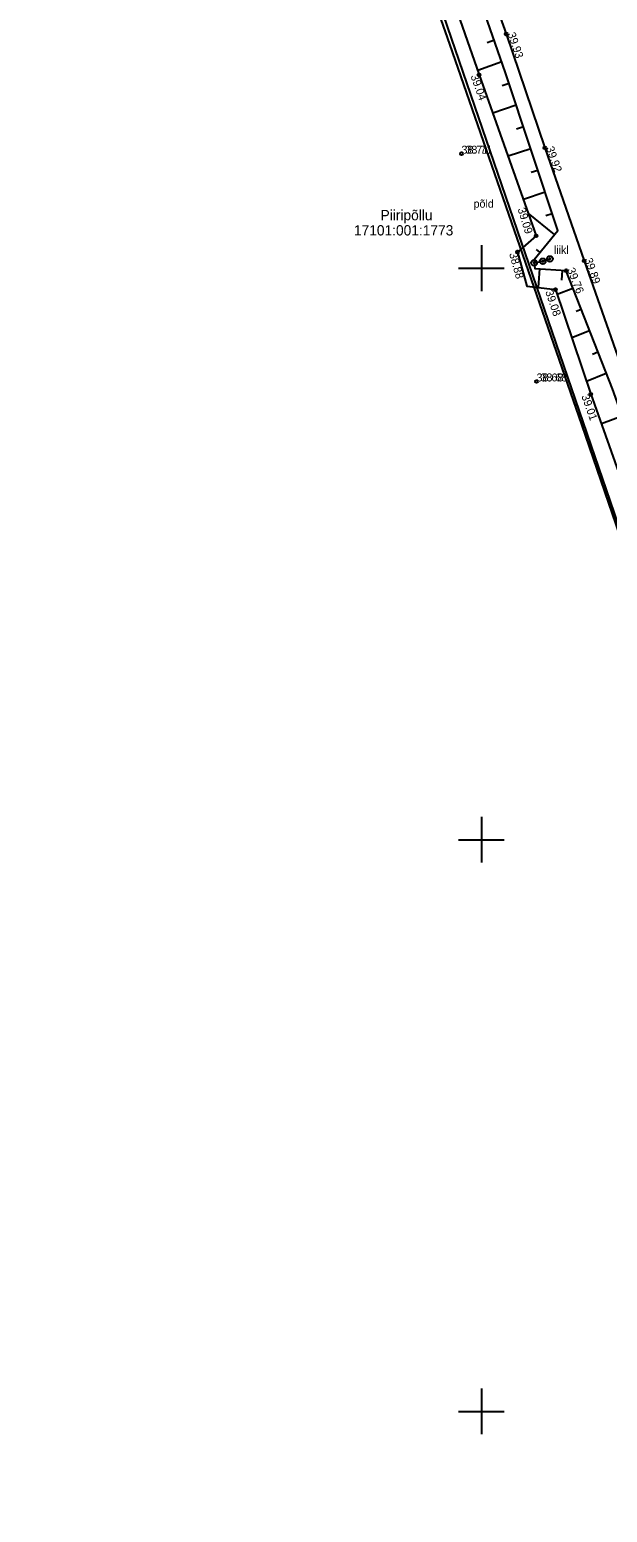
# Model space of a CAD drawing. Extents: x 627548 to 628052, y 6467984 to 6468802.
# Drawn here: x 627910.5 to 627961, y 6467991.2 to 6468120.9 of the extents above; entities that cross this region are included whole.
import ezdxf

# ---------------------------------------------------------------- set-up
doc = ezdxf.new("R2010")
doc.units = 0
for name, color, linetype in [('HALJASTUS', 7, 'Continuous'), ('KORGUS-EH2000', 7, 'Continuous'), ('LIIKLUS', 7, 'Continuous'), ('MOOTKORG-EH2000', 7, 'Continuous'), ('MOOTMPUNKT', 7, 'Continuous'), ('PIIR', 7, 'Continuous'), ('RELJEEF', 7, 'Continuous'), ('SITRASS', 7, 'Continuous'), ('TEE', 7, 'Continuous'), ('VORK', 7, 'Continuous')]:
    doc.layers.add(name, color=color, linetype=linetype)

msp = doc.modelspace()

# ---------------------------------------------------------------- linework, layer by layer
at = {"layer": 'KORGUS-EH2000'}
for centre in [(627952.16, 6468120.49), (627949.81, 6468116.9), (627955.55, 6468110.52), (627954.8, 6468102.83), (627953.15, 6468101.41), (627958.99, 6468100.64), (627957.41, 6468099.78), (627956.49, 6468098.12), (627959.58, 6468088.97)]:
    msp.add_circle(centre, 0.125, dxfattribs=at)
at = {"layer": 'LIIKLUS'}
msp.add_lwpolyline([(627954.61, 6468100.46), (627955.37, 6468100.6), (627955.99, 6468100.81)], dxfattribs=at)
for centre, radius in [((627954.61, 6468100.46), 0.25), ((627954.61, 6468100.46), 0.05), ((627955.37, 6468100.6), 0.25), ((627955.37, 6468100.6), 0.05), ((627955.99, 6468100.81), 0.25), ((627955.99, 6468100.81), 0.05)]:
    msp.add_circle(centre, radius, dxfattribs=at)
at = {"layer": 'MOOTMPUNKT'}
for centre in [(627948.25, 6468110.01), (627954.82, 6468090.09)]:
    msp.add_circle(centre, 0.125, dxfattribs=at)
at = {"layer": 'PIIR'}
msp.add_line((627946.33, 6468123.08), (627981.87, 6468019.49), dxfattribs=at)
at = {"layer": 'RELJEEF'}
for p, q in [((627951.13, 6468119.93), (627950.49, 6468119.71)), ((627951.78, 6468118.04), (627949.67, 6468117.3)), ((627952.43, 6468116.14), (627951.8, 6468115.94)), ((627953.05, 6468114.25), (627951, 6468113.56)), ((627953.68, 6468112.35), (627953.08, 6468112.15)), ((627954.31, 6468110.45), (627952.33, 6468109.79)), ((627954.94, 6468108.55), (627954.36, 6468108.36)), ((627955.57, 6468106.65), (627953.67, 6468106.02)), ((627956.39, 6468102.93), (627954.1, 6468104.82)), ((627956.19, 6468104.75), (627955.64, 6468104.57)), ((627955.11, 6468101.39), (627954.81, 6468101.64)), ((627955.07, 6468099.93), (627954.96, 6468098.3)), ((627957.06, 6468099.8), (627957.01, 6468098.95)), ((627958.01, 6468098.23), (627956.63, 6468097.69)), ((627958.74, 6468096.37), (627958.3, 6468096.2)), ((627959.47, 6468094.51), (627957.92, 6468093.9)), ((627960.2, 6468092.65), (627959.71, 6468092.45)), ((627960.93, 6468090.79), (627959.2, 6468090.1)), ((627962.33, 6468087.04), (627960.5, 6468086.38))]:
    msp.add_line(p, q, dxfattribs=at)
for points in [[(627978.29, 6468008.88), (627983.46, 6468013.68), (627984.21, 6468021.02), (627979.57, 6468037.02), (627973.98, 6468054.36), (627968.22, 6468070.61), (627961.47, 6468089.43), (627957.41, 6468099.78), (627954.7, 6468099.95), (627954.6, 6468100.77), (627956.68, 6468103.29), (627952.11, 6468117.09), (627946.48, 6468133.26), (627941.38, 6468147.78), (627936.22, 6468162.71), (627931.41, 6468176.01), (627926.77, 6468189.07), (627921.45, 6468202.33), (627917.81, 6468212.3), (627916.17, 6468214.41), (627912.96, 6468214.48), (627910.46, 6468214.18)], [(627910.97, 6468212.65), (627913.16, 6468213.42), (627915.52, 6468212.56), (627919.56, 6468201.38), (627924.57, 6468188.42), (627929.21, 6468175.58), (627934.91, 6468161.37), (627939.16, 6468147.56), (627944.58, 6468131.87), (627949.81, 6468116.9), (627954.8, 6468102.83), (627953.15, 6468101.41), (627953.98, 6468098.42), (627956.49, 6468098.12), (627959.58, 6468088.97), (627966.66, 6468069), (627971.68, 6468054.44), (627977.14, 6468035.88), (627981.19, 6468020.39), (627981.64, 6468013.54), (627978.21, 6468009.48)]]:
    msp.add_lwpolyline(points, dxfattribs=at)
at = {"layer": 'SITRASS'}
msp.add_lwpolyline([(627969.8, 6467996.72), (627973.19, 6467998.01), (627976.32, 6467999.38), (627976.44, 6468000.3), (627974.45, 6468004.59), (627974.62, 6468005.44), (627975.74, 6468006.43), (627979.44, 6468008.95), (627982.8, 6468012.81), (627983.76, 6468016.77), (627983.4, 6468018.82), (627982.47, 6468019.73), (627980.45, 6468024.26), (627973.93, 6468043.38), (627968.57, 6468057.56), (627963.8, 6468071.73), (627958.78, 6468086.33), (627947.22, 6468119.58), (627940.94, 6468137.54)], dxfattribs=at)
at = {"layer": 'TEE'}
msp.add_lwpolyline([(627948.73, 6468130.07), (627952.16, 6468120.49), (627955.55, 6468110.52), (627958.99, 6468100.64), (627962.32, 6468091.15), (627965.56, 6468081.57), (627969.01, 6468071.61), (627972.43, 6468061.58), (627975.78, 6468052.01), (627979.21, 6468042.18), (627982.52, 6468032.55), (627985.76, 6468023), (627987.72, 6468016.78), (627987.11, 6468013.91), (627990.1, 6468007.11), (627992.64, 6468000.4), (627994.5, 6467998.05), (627996.95, 6467991.17)], dxfattribs=at)
at = {"layer": 'VORK'}
for p, q in [((627950, 6468102), (627950, 6468098)), ((627948, 6468100), (627952, 6468100)), ((627950, 6468052), (627950, 6468048)), ((627948, 6468050), (627952, 6468050)), ((627950, 6468002), (627950, 6467998)), ((627948, 6468000), (627952, 6468000))]:
    msp.add_line(p, q, dxfattribs=at)

# ---------------------------------------------------------------- texts
at = {"layer": 'HALJASTUS'}
msp.add_text('põld', height=0.7, dxfattribs=at).set_placement((627949.31, 6468105.29))
at = {"layer": 'KORGUS-EH2000'}
for s, rotation, p in [(' 39.93', 288.798, (627952.2, 6468120.75)), (' 39.04', 289.5361, (627948.95, 6468117.05)), (' 39.92', 289.1797, (627955.56, 6468110.77)), (' 39.09', 287.1417, (627953.08, 6468105.42)), (' 38.88', 285.5982, (627952.35, 6468101.51)), (' 39.89', 289.3468, (627958.93, 6468101.01)), (' 39.76', 291.6826, (627957.39, 6468100.12)), (' 39.08', 288.6996, (627955.49, 6468098.19)), (' 39.01', 289.5083, (627958.65, 6468089.06))]:
    msp.add_text(s, height=0.7, rotation=rotation, dxfattribs=at).set_placement(p)
for s, p in [('38.71', (627948.6, 6468110.01)), ('38.68', (627955.17, 6468090.09))]:
    msp.add_text(s, height=0.7, dxfattribs=at).set_placement(p)
at = {"layer": 'LIIKLUS'}
msp.add_text('liikl', height=0.7, dxfattribs=at).set_placement((627956.34, 6468101.25))
at = {"layer": 'MOOTKORG-EH2000'}
for s, p in [('38.71', (627948.25, 6468110.01)), ('38.68', (627954.82, 6468090.09))]:
    msp.add_text(s, height=0.7, dxfattribs=at).set_placement(p)
at = {"layer": 'PIIR'}
for s, p in [('Piiripõllu', (627941.17, 6468104.19)), ('17101:001:1773', (627938.84, 6468102.86))]:
    msp.add_text(s, height=0.9, dxfattribs=at).set_placement(p)

doc.saveas('drawing.dxf')
